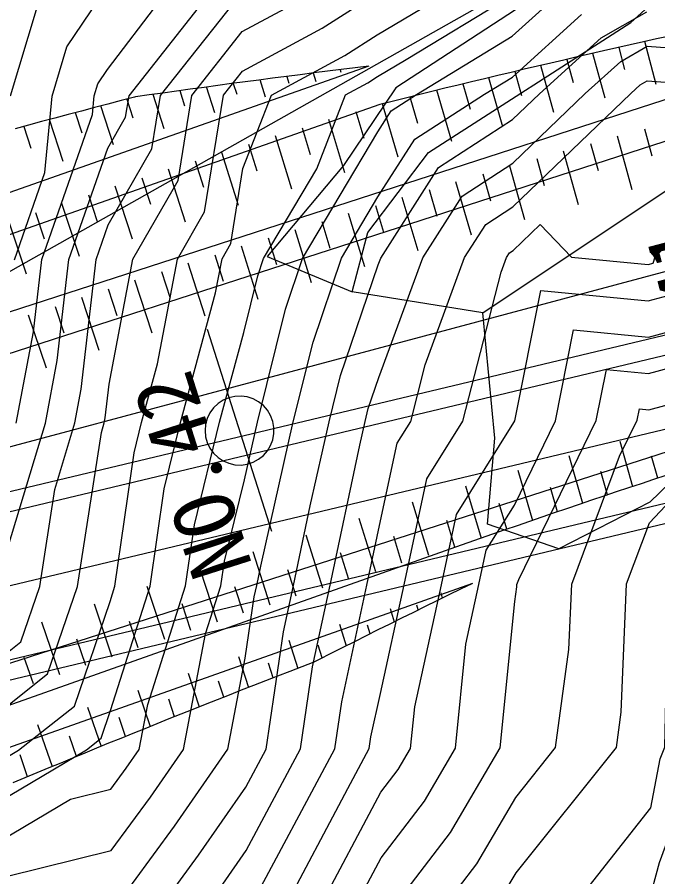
# Model space of a CAD drawing. Extents: x 42655 to 43811, y -141820 to -141156.
# Drawn here: x 43241.93 to 43266.1, y -141374.58 to -141342.18 of the extents above; entities that cross this region are included whole.
import ezdxf

# ---------------------------------------------------------------- set-up
doc = ezdxf.new("R2010")
doc.units = 0
for name, color, linetype in [('D-BMK-HTXT_1', 7, 'Continuous'), ('D-BMK_1', 7, 'Continuous'), ('D-STR-STR5_1', 7, 'Continuous'), ('D-STR_1', 7, 'Continuous'), ('ZE_HICN', 7, 'Continuous'), ('ZE_LWCN', 7, 'Continuous'), ('地形', 7, 'Continuous')]:
    doc.layers.add(name, color=color, linetype=linetype)

msp = doc.modelspace()

# ---------------------------------------------------------------- linework, layer by layer
at = {"layer": 'D-BMK-HTXT_1'}
for p, q in [((43274.802, -141333.044), (43130.975, -141414.265)), ((43251.533, -141361.568), (43249.106, -141353.945))]:
    msp.add_line(p, q, dxfattribs=at)
msp.add_lwpolyline([(43249.02, -141357.757), (43249.04, -141357.989), (43249.102, -141358.214), (43249.204, -141358.424), (43249.341, -141358.612), (43249.509, -141358.773), (43249.704, -141358.902), (43249.918, -141358.993), (43250.145, -141359.045), (43250.378, -141359.056), (43250.609, -141359.024), (43250.831, -141358.952), (43251.036, -141358.842), (43251.218, -141358.696), (43251.371, -141358.521), (43251.491, -141358.321), (43251.573, -141358.103), (43251.614, -141357.873), (43251.614, -141357.64), (43251.573, -141357.411), (43251.491, -141357.193), (43251.371, -141356.993), (43251.218, -141356.817), (43251.036, -141356.672), (43250.83, -141356.561), (43250.609, -141356.489), (43250.378, -141356.458), (43250.145, -141356.469), (43249.918, -141356.52), (43249.704, -141356.612), (43249.509, -141356.74), (43249.341, -141356.902), (43249.204, -141357.09), (43249.102, -141357.3), (43249.04, -141357.525), (43249.02, -141357.757)], dxfattribs=at)
at = {"layer": 'D-BMK_1'}
msp.add_lwpolyline([(43339.878, -141340.165), (43219.961, -141368.793)], dxfattribs=at)
at = {"layer": 'D-STR-STR5_1'}
for p, q in [((43264.621, -141343.317), (43264.845, -141344.144)), ((43266.035, -141344.712), (43265.602, -141343.096)), ((43264.104, -141345.234), (43263.641, -141343.54)), ((43255.124, -141344.045), (43255.121, -141344.033)), ((43262.176, -141345.766), (43261.682, -141343.994)), ((43262.661, -141343.765), (43262.901, -141344.632)), ((43253.208, -141344.616), (43253.107, -141344.281)), ((43254.114, -141344.156), (43254.14, -141344.242)), ((43260.704, -141344.224), (43260.958, -141345.13)), ((43250.085, -141344.672), (43250.212, -141345.081)), ((43251.294, -141345.196), (43251.093, -141344.539)), ((43252.1, -141344.409), (43252.175, -141344.657)), ((43258.744, -141344.693), (43259.015, -141345.638)), ((43260.251, -141346.308), (43259.726, -141344.457)), ((43248.071, -141344.945), (43248.249, -141345.515)), ((43249.383, -141345.786), (43249.078, -141344.807)), ((43258.321, -141346.861), (43257.763, -141344.932)), ((43246.066, -141345.261), (43246.294, -141345.974)), ((43247.474, -141346.385), (43247.063, -141345.086)), ((43256.739, -141345.184), (43257.027, -141346.169)), ((43245.569, -141346.993), (43245.094, -141345.516)), ((43256.309, -141347.448), (43255.716, -141345.438)), ((43244.122, -141345.774), (43244.37, -141346.537)), ((43254.703, -141345.734), (43255.003, -141346.74)), ((43242.18, -141346.295), (43242.448, -141347.109)), ((43243.667, -141347.61), (43243.151, -141346.033)), ((43254.296, -141348.047), (43253.692, -141346.036)), ((43252.682, -141346.341), (43252.986, -141347.346)), ((43265.597, -141346.383), (43265.871, -141347.396)), ((43250.663, -141346.959), (43250.973, -141347.962)), ((43252.287, -141348.657), (43251.672, -141346.649)), ((43263.56, -141346.939), (43263.84, -141347.951)), ((43265.132, -141348.685), (43264.578, -141346.66)), ((43250.28, -141349.277), (43249.655, -141347.272)), ((43263.107, -141349.244), (43262.543, -141347.221)), ((43248.648, -141347.587), (43248.963, -141348.589)), ((43261.527, -141347.506), (43261.812, -141348.516)), ((43248.277, -141349.907), (43247.642, -141347.905)), ((43261.086, -141349.813), (43260.511, -141347.793)), ((43246.636, -141348.226), (43246.956, -141349.226)), ((43259.497, -141348.083), (43259.786, -141349.092)), ((43246.277, -141350.547), (43245.631, -141348.549)), ((43259.067, -141350.393), (43258.483, -141348.376)), ((43244.627, -141348.875), (43244.953, -141349.873)), ((43257.469, -141348.671), (43257.764, -141349.679)), ((43244.28, -141351.198), (43243.624, -141349.203)), ((43257.052, -141350.983), (43256.457, -141348.969)), ((43242.622, -141349.534), (43242.953, -141350.53)), ((43255.445, -141349.269), (43255.745, -141350.275)), ((43242.287, -141351.859), (43241.621, -141349.867)), ((43253.424, -141349.878), (43253.729, -141350.883)), ((43255.04, -141351.583), (43254.434, -141349.572)), ((43253.03, -141352.194), (43252.414, -141350.187)), ((43251.406, -141350.498), (43251.716, -141351.501)), ((43251.025, -141352.816), (43250.398, -141350.811)), ((43249.391, -141351.128), (43249.707, -141352.129)), ((43249.022, -141353.447), (43248.385, -141351.446)), ((43247.379, -141351.768), (43247.701, -141352.768)), ((43247.022, -141354.09), (43246.375, -141352.092)), ((43245.371, -141352.419), (43245.698, -141353.417)), ((43245.026, -141354.742), (43244.369, -141352.748)), ((43243.367, -141353.08), (43243.698, -141354.076)), ((43243.034, -141355.405), (43242.366, -141353.414)), ((43264.665, -141358.153), (43265.147, -141359.866)), ((43262.741, -141358.699), (43263.257, -141360.499)), ((43266.093, -141359.552), (43265.861, -141358.718)), ((43260.82, -141359.255), (43261.372, -141361.142)), ((43264.202, -141360.181), (43263.952, -141359.303)), ((43258.842, -141359.839), (43259.431, -141361.815)), ((43262.314, -141360.82), (43262.047, -141359.898)), ((43256.831, -141360.443), (43257.441, -141362.453)), ((43260.401, -141361.478), (43260.116, -141360.512)), ((43254.823, -141361.059), (43255.444, -141363.065)), ((43258.441, -141362.151), (43258.139, -141361.145)), ((43252.819, -141361.685), (43253.45, -141363.688)), ((43256.442, -141362.758), (43256.134, -141361.754)), ((43250.818, -141362.321), (43251.459, -141364.321)), ((43254.447, -141363.375), (43254.134, -141362.373)), ((43248.82, -141362.969), (43249.472, -141364.965)), ((43252.454, -141364.003), (43252.136, -141363.002)), ((43246.825, -141363.626), (43247.489, -141365.619)), ((43250.465, -141364.641), (43250.142, -141363.643)), ((43258.877, -141363.629), (43258.871, -141363.609)), ((43257.907, -141363.879), (43257.967, -141364.073)), ((43244.835, -141364.295), (43245.508, -141366.284)), ((43248.48, -141365.291), (43248.151, -141364.293)), ((43255.995, -141364.465), (43256.151, -141364.969)), ((43257.058, -141364.52), (43257.004, -141364.345)), ((43242.847, -141364.974), (43243.532, -141366.959)), ((43246.498, -141365.95), (43246.164, -141364.955)), ((43254.086, -141365.06), (43254.342, -141365.873)), ((43255.246, -141365.42), (43255.143, -141365.091)), ((43244.52, -141366.62), (43244.18, -141365.627)), ((43252.18, -141365.665), (43252.518, -141366.721)), ((43253.439, -141366.329), (43253.286, -141365.845)), ((43242.545, -141367.301), (43242.2, -141366.309)), ((43250.276, -141366.28), (43250.656, -141367.443)), ((43251.586, -141367.081), (43251.407, -141366.526)), ((43248.377, -141366.905), (43248.798, -141368.175)), ((43249.726, -141367.808), (43249.526, -141367.199)), ((43246.48, -141367.539), (43246.944, -141368.915)), ((43247.87, -141368.544), (43247.649, -141367.882)), ((43244.586, -141368.183), (43245.095, -141369.665)), ((43246.019, -141369.289), (43245.776, -141368.574)), ((43242.696, -141368.836), (43243.25, -141370.424)), ((43244.172, -141370.043), (43243.906, -141369.276)), ((43242.329, -141370.807), (43242.04, -141369.987))]:
    msp.add_line(p, q, dxfattribs=at)
for points in [[(43275.994, -141342.176), (43216.96, -141361.274)], [(43266.55, -141342.885), (43266.05, -141342.996), (43265.55, -141343.107), (43265.051, -141343.22), (43264.551, -141343.332), (43264.052, -141343.446), (43263.553, -141343.56), (43263.053, -141343.675), (43262.554, -141343.79), (43262.056, -141343.906), (43261.557, -141344.023), (43261.058, -141344.14), (43260.56, -141344.258), (43260.061, -141344.377), (43259.563, -141344.496), (43259.065, -141344.616), (43258.567, -141344.736), (43258.069, -141344.857), (43257.571, -141344.979), (43257.073, -141345.101), (43256.576, -141345.224), (43256.078, -141345.348), (43255.617, -141345.463)], [(43276.345, -141343.634), (43217.529, -141362.662)], [(43255.193, -141344.024), (43215.594, -141357.943)], [(43255.193, -141344.024), (43254.675, -141344.087), (43254.158, -141344.15), (43253.64, -141344.214), (43253.122, -141344.279), (43252.605, -141344.344), (43252.087, -141344.41), (43251.569, -141344.477), (43251.052, -141344.544), (43250.534, -141344.612), (43250.016, -141344.681), (43249.498, -141344.75), (43248.981, -141344.82), (43248.463, -141344.891), (43247.945, -141344.963), (43247.427, -141345.035), (43246.909, -141345.108), (43246.391, -141345.181), (43246.354, -141345.186), (43245.854, -141345.317), (43245.354, -141345.448), (43244.855, -141345.579), (43244.355, -141345.712), (43243.856, -141345.845), (43243.356, -141345.978), (43242.857, -141346.112), (43242.358, -141346.247), (43241.86, -141346.382)], [(43255.617, -141345.463), (43216.163, -141359.331)], [(43266.399, -141359.452), (43265.93, -141359.606), (43265.462, -141359.761), (43264.994, -141359.917), (43264.526, -141360.073), (43264.058, -141360.229), (43263.591, -141360.387), (43263.124, -141360.545), (43262.657, -141360.703), (43262.19, -141360.862), (43261.723, -141361.022), (43261.257, -141361.182), (43260.791, -141361.343), (43260.325, -141361.504), (43259.859, -141361.666), (43259.394, -141361.828), (43258.928, -141361.991), (43258.675, -141362.08)], [(43258.675, -141362.08), (43222.45, -141374.906)], [(43259.106, -141363.517), (43223.019, -141376.294)], [(43259.106, -141363.517), (43258.659, -141363.735), (43258.213, -141363.953), (43257.767, -141364.171), (43257.321, -141364.39), (43256.876, -141364.61), (43256.431, -141364.83), (43255.987, -141365.051), (43255.542, -141365.272), (43255.099, -141365.494), (43254.655, -141365.716), (43254.212, -141365.939), (43253.769, -141366.162), (43253.327, -141366.386), (43253.126, -141366.488), (43252.669, -141366.663), (43252.211, -141366.839), (43251.755, -141367.016), (43251.298, -141367.193), (43250.841, -141367.371), (43250.385, -141367.549), (43249.929, -141367.728), (43249.474, -141367.907), (43249.018, -141368.087), (43248.563, -141368.268), (43248.108, -141368.449), (43247.654, -141368.63), (43247.199, -141368.813), (43246.745, -141368.995), (43246.291, -141369.179), (43245.838, -141369.362), (43245.384, -141369.547), (43244.931, -141369.732), (43244.479, -141369.917), (43244.026, -141370.103), (43243.574, -141370.29), (43243.122, -141370.477), (43242.67, -141370.665), (43242.219, -141370.853), (43241.767, -141371.042)]]:
    msp.add_lwpolyline(points, dxfattribs=at)
at = {"layer": 'D-STR_1'}
for points in [[(43339.6, -141336.676), (43218.633, -141365.555)], [(43339.659, -141337.424), (43218.917, -141366.249)], [(43317.868, -141337.995), (43218.254, -141364.63)], [(43340.097, -141342.907), (43221.004, -141371.338)], [(43340.157, -141343.654), (43221.288, -141372.032)], [(43280.321, -141354.098), (43221.668, -141372.957)]]:
    msp.add_lwpolyline(points, dxfattribs=at)
at = {"layer": 'ZE_HICN'}
for points in [[(43241.9, -141357.482), (43242.545, -141354.033), (43242.859, -141351.315), (43244.774, -141345.842), (43244.841, -141345.143), (43244.975, -141344.693), (43245.343, -141344.144), (43249.284, -141338.959), (43250.403, -141338.087), (43253.103, -141336.06), (43255.47, -141333.538), (43257.102, -141332.76), (43259.846, -141331.894), (43260.544, -141330.544), (43262.971, -141326.569), (43265.588, -141321.254)], [(43249.689, -141374.859), (43250.57, -141373.588), (43252.624, -141369.757), (43253.076, -141366.667), (43253.74, -141363.589), (43254.854, -141358.308), (43255.054, -141357.42), (43255.176, -141356.93), (43255.574, -141355.76), (43257.228, -141351.247), (43258.712, -141348.917), (43260.625, -141347.681), (43263.355, -141345.055), (43264.697, -141343.841), (43265.692, -141343.273), (43269.564, -141343.552), (43270.774, -141341.968), (43272.722, -141338.849), (43274.151, -141336.8), (43275.833, -141335.898), (43278.271, -141332.66), (43277.915, -141330.107), (43278.412, -141326.496), (43276.737, -141321.518)], [(43255.992, -141375.904), (43258.278, -141372.907), (43260.154, -141369.721), (43260.702, -141364.205), (43260.778, -141363.65), (43260.782, -141363.556), (43260.851, -141363.37), (43263.775, -141357.379), (43264.16, -141355.452), (43265.75, -141355.603), (43268.727, -141354.803), (43269.864, -141351.187), (43270.813, -141350.209), (43274.319, -141349.256), (43275.461, -141344.998), (43275.874, -141344.402), (43278.608, -141342.146), (43280.936, -141339.002)], [(43240.388, -141372.252), (43244.544, -141369.795), (43245.101, -141369.355), (43245.457, -141368.311), (43246.954, -141363.621), (43247.482, -141359.956), (43248.097, -141357.453), (43249.414, -141352.564), (43249.659, -141351.283), (43249.989, -141350.708), (43250.449, -141347.879), (43251.526, -141345.111), (43254.296, -141343.62), (43255.514, -141342.839), (43259.123, -141340.691)]]:
    msp.add_lwpolyline(points, dxfattribs=at)
at = {"layer": 'ZE_LWCN'}
for points in [[(43250.656, -141375.837), (43253.918, -141369.751), (43254.177, -141367.987), (43255.126, -141363.582), (43255.601, -141361.333), (43256.265, -141358.237), (43256.781, -141357.412), (43257.326, -141355.285), (43258.808, -141351.24), (43259.605, -141349.988), (43260.632, -141349.325), (43265.079, -141345.047), (43265.435, -141344.726), (43265.698, -141344.575), (43270.719, -141344.937), (43270.787, -141344.848), (43274.539, -141338.84), (43275.137, -141337.982), (43275.841, -141337.605), (43279.569, -141332.654), (43279.024, -141328.751), (43279.335, -141326.492), (43278.288, -141323.378)], [(43240.363, -141367.073), (43242.073, -141365.722), (43242.784, -141363.64), (43243.351, -141359.979), (43244.112, -141357.471), (43244.35, -141356.199), (43244.915, -141351.305), (43245.371, -141350.001), (43247.014, -141347.139), (43247.341, -141345.131), (43250.418, -141341.231), (43251.721, -141340.53), (43254.205, -141338.936), (43255.002, -141338.338), (43255.49, -141337.817), (43256.99, -141337.102), (43260.564, -141334.831), (43261.635, -141334.04), (43263.823, -141332.728), (43265.626, -141329.205), (43266.14, -141327.189), (43266.702, -141326.552), (43268.346, -141323.708)], [(43241.831, -141351.32), (43242.98, -141348.036), (43243.256, -141345.15), (43243.81, -141343.294), (43245.329, -141341.032), (43246.896, -141338.97), (43250.394, -141336.242), (43252.153, -141334.921), (43254.169, -141332.773), (43255.462, -141331.865), (43258.914, -141330.775), (43260.53, -141327.651), (43261.186, -141326.578), (43262.182, -141324.555)], [(43241.594, -141362.127), (43243.006, -141357.477), (43243.448, -141355.116), (43243.887, -141351.31), (43245.357, -141347.108), (43246.022, -141345.949), (43246.155, -141345.136), (43250.411, -141339.743), (43250.862, -141339.5), (43251.723, -141338.948), (43254.052, -141337.199), (43255.48, -141335.677), (43259.864, -141333.587), (43260.556, -141333.147), (43260.763, -141332.994), (43261.187, -141332.74), (43262.241, -141330.681), (43264.756, -141326.561), (43265.605, -141324.837)], [(43240.373, -141369.074), (43243.082, -141366.933), (43244.209, -141363.634), (43245.108, -141357.831), (43245.218, -141357.466), (43245.253, -141357.281), (43245.399, -141356.01), (43246.301, -141351.298), (43248.006, -141348.329), (43248.527, -141345.125), (43250.425, -141342.72), (43252.579, -141341.56), (43255.499, -141339.686), (43256.781, -141338.924), (43260.572, -141336.515), (43262.507, -141335.086), (43265.644, -141333.204), (43266.053, -141332.717), (43267.153, -141328.404), (43268.796, -141326.542), (43269.579, -141325.187)], [(43259.866, -141325.79), (43259.571, -141326.585), (43257.982, -141329.657), (43255.455, -141330.455), (43252.142, -141332.783), (43251.204, -141333.782), (43250.386, -141334.396), (43246.741, -141337.239), (43245.316, -141338.388), (43244.993, -141338.587), (43244.601, -141338.981), (43242.644, -141341.896), (43241.671, -141345.158)], [(43253.251, -141375.916), (43255.648, -141371.394), (43256.302, -141370.537), (43256.773, -141369.737), (43256.929, -141368.166), (43257.937, -141363.569), (43258.505, -141360.923), (43260.671, -141357.456), (43260.701, -141357.393), (43261.682, -141352.479), (43265.737, -141352.864), (43266.859, -141352.562), (43267.288, -141351.2), (43270.8, -141347.575), (43272.527, -141347.106), (43273.089, -141345.01), (43275.858, -141341.007), (43276.925, -141340.126), (43277.889, -141338.824), (43280.916, -141334.723)], [(43254.572, -141375.91), (43255.66, -141373.859), (43257.29, -141371.722), (43258.463, -141369.729), (43258.853, -141365.814), (43259.346, -141363.562), (43259.624, -141362.267), (43260.685, -141360.568), (43262.238, -141357.386), (43262.921, -141353.966), (43265.744, -141354.233), (43267.793, -141353.683), (43268.576, -141351.194), (43270.807, -141348.892), (43273.423, -141348.181), (43274.275, -141345.004), (43275.866, -141342.705), (43277.766, -141341.136), (43279.484, -141338.817), (43280.926, -141336.863)], [(43251.929, -141375.923), (43254.404, -141371.255), (43255.213, -141369.745), (43255.277, -141369.307), (43255.631, -141367.667), (43256.527, -141363.576), (43257.385, -141359.58), (43258.745, -141357.403), (43260.184, -141351.79), (43260.388, -141351.232), (43260.498, -141351.06), (43260.64, -141350.968), (43261.653, -141349.994), (43262.841, -141351.221), (43265.731, -141351.495), (43265.925, -141351.442), (43266, -141351.206), (43270.794, -141346.258), (43271.631, -141346.031), (43271.903, -141345.015), (43275.85, -141339.309)], [(43257.891, -141375.895), (43259.266, -141374.092), (43260.737, -141371.593), (43262.241, -141369.711), (43262.746, -141366.011), (43262.85, -141363.546), (43264.655, -141358.718), (43265.313, -141357.372), (43265.399, -141356.938), (43265.756, -141356.972), (43269.66, -141355.923), (43270.822, -141352.23), (43272.102, -141351.177), (43275.215, -141350.331), (43275.89, -141347.817), (43277.226, -141344.99), (43279.449, -141343.155), (43280.946, -141341.134)], [(43240.381, -141370.757), (43241.987, -141369.807), (43244.092, -141368.144), (43245.438, -141364.203), (43245.622, -141363.627), (43246.348, -141358.595), (43246.627, -141357.46), (43247.224, -141355.242), (43247.98, -141351.291), (43248.998, -141349.518), (43249.713, -141345.12), (43250.432, -141344.208), (43253.438, -141342.59), (43255.506, -141341.262)], [(43240.395, -141373.748), (43243.944, -141371.649), (43245.471, -141371.273), (43246.047, -141370.489), (43246.535, -141369.785), (43246.86, -141368.084), (43248.286, -141363.614), (43248.617, -141361.317), (43249.568, -141357.446), (43250.478, -141354.065), (43251.007, -141351.929), (43251.23, -141351.275), (43253.234, -141347.893), (43254.322, -141345.098), (43255.155, -141344.649), (43255.521, -141344.415), (43256.606, -141343.769), (43260.595, -141341.346)], [(43241.569, -141374.554), (43245.482, -141373.59), (43246.957, -141371.582), (43248.209, -141369.778), (43249.04, -141365.417), (43249.617, -141363.608), (43249.752, -141362.678), (43250.504, -141359.613), (43250.995, -141357.439), (43252.049, -141353.179), (43252.7, -141351.268), (43255.531, -141346.492), (43256.033, -141345.703), (43256.989, -141345.085), (43260.602, -141342.891), (43262.486, -141341.188)], [(43245.493, -141375.907), (43247.868, -141372.674), (43249.883, -141369.77), (43250.536, -141366.343), (43250.875, -141364.026), (43250.967, -141363.602), (43251.121, -141362.873), (43252.348, -141357.433), (43253.091, -141354.429), (43254.171, -141351.261), (43255.542, -141348.947), (43256.926, -141346.774), (43259.559, -141345.073), (43260.609, -141344.435), (43263.223, -141342.072)], [(43247.178, -141375.945), (43248.778, -141373.766), (43250.559, -141371.2), (43251.329, -141369.763), (43251.976, -141365.347), (43252.353, -141363.595), (43252.987, -141360.591), (43253.701, -141357.426), (43254.134, -141355.68), (43255.554, -141351.51), (43255.648, -141351.254), (43257.819, -141347.846), (43260.617, -141346.038), (43261.63, -141345.064), (43263.96, -141342.957), (43265.686, -141341.97)], [(43260.254, -141375.277), (43260.751, -141374.433), (43264.533, -141369.701), (43264.714, -141368.372), (43264.919, -141363.536), (43265.777, -141361.242), (43269.445, -141357.352), (43270.594, -141357.043), (43270.841, -141356.258), (43273.578, -141354.005), (43275.912, -141352.667), (43276.09, -141351.38), (43280.406, -141351.138), (43277.035, -141349.778), (43279.303, -141344.98), (43280.291, -141344.165), (43280.956, -141343.267)], [(43262.768, -141375.872), (43265.827, -141371.973), (43266.179, -141370.13), (43266.355, -141369.692), (43266.478, -141364.36), (43267.4, -141363.524), (43270.857, -141359.618), (43272.083, -141358.829), (43275.938, -141358.014), (43276.206, -141357.32), (43276.892, -141352.342), (43280.998, -141352.112)]]:
    msp.add_lwpolyline(points, dxfattribs=at)
at = {"layer": '地形'}
for points in [[(43273.079, -141323.322), (43269.743, -141326.702), (43267.594, -141329.35), (43267.503, -141331.725), (43268.052, -141334.374), (43267.728, -141337.079), (43262.426, -141340.779), (43256.21, -141344.843), (43254.244, -141347.766), (43251.365, -141351.191), (43254.566, -141352.527)], [(43259.49, -141353.323), (43254.566, -141352.527), (43255.16, -141350.289), (43257.446, -141347.275), (43265.079, -141342.38), (43269.147, -141338.68), (43270.2, -141337.253), (43275.228, -141330.629), (43276.508, -141327.935), (43280.347, -141325.971)], [(43294.351, -141331.831), (43287.212, -141332.387), (43284.616, -141334.517), (43283.225, -141336.926), (43283.04, -141340.261), (43281.649, -141344.615), (43277.477, -141350.173), (43268.484, -141357.862), (43265.795, -141360.456), (43262.364, -141362.216), (43259.675, -141361.29), (43259.954, -141358.047), (43259.49, -141353.323), (43267.278, -141348.135), (43273.583, -141344.43), (43277.292, -141341.558), (43278.126, -141337.667), (43277.57, -141330.534), (43278.96, -141328.403), (43282.854, -141326.551), (43290.086, -141326.643), (43295.186, -141327.014), (43294.351, -141331.831)], [(43288.267, -141354.855), (43285.848, -141365.022), (43286.267, -141373.121), (43283.514, -141385.454), (43279.342, -141386.896), (43276.006, -141392.479), (43271.085, -141402.146), (43263.495, -141406.646), (43258.074, -141408.063), (43249.233, -141407.397), (43252.319, -141404.646), (43256.322, -141401.063), (43260.326, -141396.896), (43262.077, -141391.23), (43264.079, -141381.71), (43266.164, -141374.043), (43268.332, -141368.119), (43272.002, -141363.119), (43277.924, -141357.869), (43283.274, -141352.393), (43288.267, -141354.855)]]:
    msp.add_lwpolyline(points, dxfattribs=at)

# ---------------------------------------------------------------- texts
at = {"layer": 'D-BMK-HTXT_1'}
for s, rotation, p in [('NO.41', 104.7983, (43269.758, -141357.276)), ('NO.42', 107.6631, (43250.812, -141362.847))]:
    msp.add_text(s, height=2.3065, rotation=rotation, dxfattribs=at).set_placement(p)

doc.saveas('drawing.dxf')
